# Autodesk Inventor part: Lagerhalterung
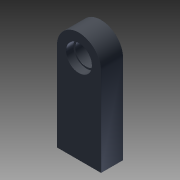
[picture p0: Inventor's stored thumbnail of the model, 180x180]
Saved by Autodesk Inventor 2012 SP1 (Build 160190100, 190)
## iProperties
Created: 2012-10
Part Number: Lagerhalterung
Material: Default
Document SubType Name: Modeling
Designer: Dominic Mähling
Density: 1 g/cm^3
Author: Dominic Mähling
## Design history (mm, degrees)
derived "Funkenstrecke master.ipt"
feature "Lagerhalterung::Funkenstrecke master.ipt" dims "d0" = 10
tag "Bezeichnung1"
node "Volumenkörper1"
